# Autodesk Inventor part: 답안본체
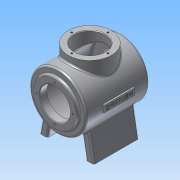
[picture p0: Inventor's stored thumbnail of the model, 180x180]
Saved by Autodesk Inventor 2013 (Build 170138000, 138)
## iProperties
Created: 2015-01
Part Number: 답안본체
Material: 알루미늄 6061
Document SubType Name: Modeling
Designer: Administrator
Density: 2.71 g/cm^3
Mass: 1021.13 g
Surface Area: 1060.37 cm^2
Volume: 376.8 cm^3
Author: Administrator
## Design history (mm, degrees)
sketch "스케치1"
  geometry: C1 r 50 at (0, 0); C2 r 45 at (0, 0); 1 further point
  constraints: 2 centre point, 2 coincident
  dimensions: "d0" = 100 diameter of C1; "d1" = 90 diameter of C2
extrude "돌출1" new body sketch "스케치1" stored distance "d2" = 112; taper "d3" = 0 deg
extrude "돌출2" cut sketch "스케치1" distance "d4" = 48; taper "d5" = 0 deg; dims "d73" = 49, "d74" = 0
sketch "스케치2"
  geometry: C1 r 50 at (0, 0) reference; C2 r 38 at (0, 0)
  constraints: 1 centre point, 1 coincident
  dimensions: "d6" = 76 diameter of C2
extrude "돌출3" join sketch "스케치2" distance "d7" = 5; taper "d8" = 0 deg
hole "구멍1" diameter "d11" = 54; stored, may be unused: countersink angle "d15" = 90 deg, drill point angle "d17" = 118 deg; dims "d9" = 10, "d10" = 10, "d12" = 6, "d13" = 4, "d14" = 2, "d16" = 8
sketch "스케치3"
  geometry: C1 r 27 at (0, 0) reference; 1 further point
  constraints: 1 vertical alignment
  dimensions: "d18" = 32 distance of C1.centre point (0, 32)
hole "구멍2" sketch "스케치3" at (0, 32) diameter "d19" = 3.242; stored, may be unused: countersink angle "d23" = 90 deg, drill point angle "d25" = 118 deg; dims "d20" = 8, "d21" = 4, "d22" = 2, "d24" = 10
sketch "스케치4"
  geometry: L1 (-48, -80)-(-34, -80); L2 (-34, -80)-(-27.282, -41.901); L3 (-48, -80)-(-39.336, -30.865); C1 r 45 at (0, 0) reference; A1 r 50 centre (0, 0) between (-39.336, -30.865) and (-27.282, -41.901) reference; 1 further point
  constraints: 6 end point, 2 point on circle, 1 horizontal, 1 parallel
  dimensions: "d29" = 14 distance of L1.start L1.end; "d31" = 80 distance from line of L1 point (0, 0); "d32" = 48 horizontal distance of point (0, 0) L1.start; "d33" = 80 deg angle of L1 L2
extrude "돌출4" join sketch "스케치4" stored distance "d34" = 80; taper "d35" = 0 deg
node "작업 평면1"
sketch "스케치5"
  geometry: L1 (38, -61)-(-38, -61) reference; C1 r 38 at (0, -1); 1 further point
  constraints: 1 centre point, 1 vertical alignment
  dimensions: "d37" = 76 diameter of C1; "d38" = 60 distance from line of C1.centre L1
extrude "돌출5" join sketch "스케치5" stored distance "d39" = 80; taper "d40" = 0 deg
sketch "스케치6"
  geometry: L1 (-38, -62)-(38, -62) reference; C1 r 27 at (0, 0); C2 r 38 at (0, 0) reference; 1 further point
  constraints: 1 centre point, 1 coincident
  dimensions: "d41" = 54 diameter of C1
extrude "돌출6" cut sketch "스케치6" distance "d42" = 50; taper "d43" = 0 deg
sketch "스케치7"
  geometry: C1 r 38 at (0, 0) reference; C2 r 27 at (0, 0) reference; 1 further point
  constraints: 1 vertical alignment
  dimensions: "d71" = 32 distance of C2.centre point (0, 32)
hole "구멍3" sketch "스케치7" at (0, 32) diameter "d45" = 3.242; stored, may be unused: countersink angle "d49" = 90 deg, drill point angle "d51" = 118 deg; dims "d46" = 8, "d47" = 4, "d48" = 2, "d50" = 10
node "작업 평면3"
  node "작업 평면2"
sketch "스케치8"
  geometry: L1 (6, 26)-(-6, 26); L2 (-6, 26)-(-6, -28); L3 (-6, -28)-(6, -28); L4 (6, -28)-(6, 26); L5 (38, 61)-(-38, 61) reference; L6 (6, -1)-(20.992, -1); 2 further points
  constraints: 10 end point, 3 parallel, 2 midpoint, 1 horizontal, 1 perpendicular, 1 vertical alignment
  dimensions: "d56" = 12 distance of L3.end L2.end; "d57" = 54 distance of L2.end L1.end; "d59" = 62 distance between parallel lines of L6 L5
extrude "돌출7" join sketch "스케치8" stored distance "d60" = 50; taper "d61" = 0 deg
sketch "스케치9"
  geometry: L1 (-26, 6)-(-26, -6) reference; L2 (28, 6)-(-26, 6) reference; 4 further points
  constraints: 2 midpoint, 1 horizontal alignment, 1 vertical alignment, 1 other
feature "엠보싱1" sketch "스케치9" dims "d3" = 0, "d25" = 118 deg, "d62" = 0.5, "d63" = 0
chamfer "모따기1" distance "d64" = 1; stored, may be unused: second distance "d65" = 2, angle "d66" = 45 deg
fillet "모깎기1" dims "d67" = 3
fillet "모깎기2" dims "d68" = 3
fillet "모깎기3" dims "d69" = 3
fillet "모깎기4" dims "d70" = 3
node "솔리드1"
pattern_circular "원형 패턴1" dims angle "d27" = 360 deg
mirror "대칭1"
mirror "대칭2"
pattern_circular "원형 패턴2" dims angle "d53" = 360 deg
node "절단 모서리 투영1"
other parameters: "d36" = 62, "d55" = 2
